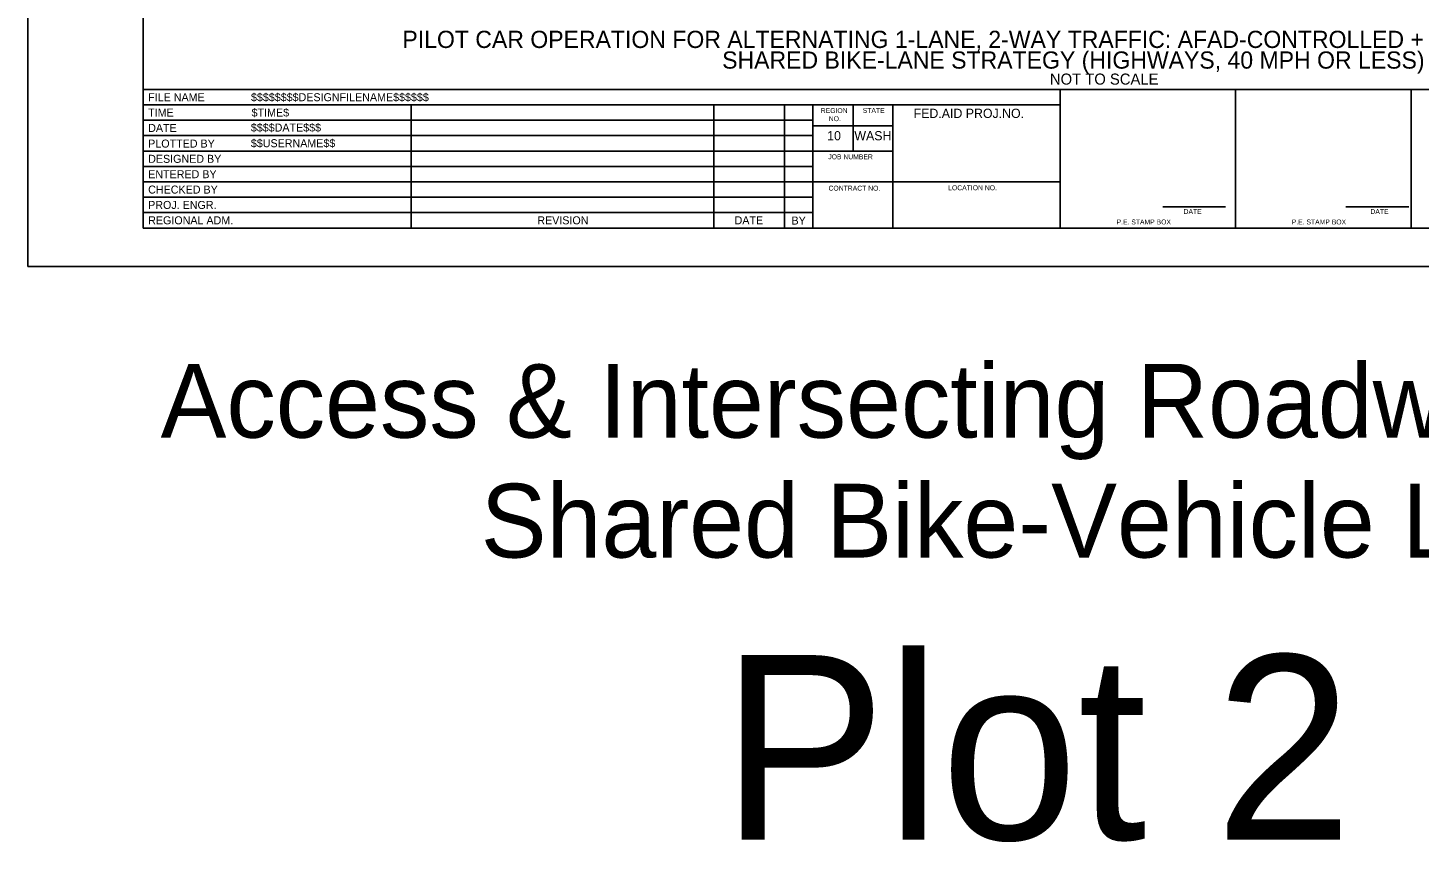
# Model space of a CAD drawing. Extents: x 99999.1 to 100095.7, y 99995 to 100010.7.
# Drawn here: x 100019.06 to 100030.38, y 99995.01 to 100001.63 of the extents above; entities that cross this region are included whole.
import ezdxf

# ---------------------------------------------------------------- set-up
doc = ezdxf.new("R2010")
doc.units = 0
for name, color, linetype in [('SH_DE_DetailHeading1Text', 7, 'Continuous'), ('SH_GI_PlotLimits', 7, 'Continuous'), ('SH_GI_SheetBorder', 7, 'Continuous'), ('SH_GI_SheetLocationText', 7, 'Continuous'), ('SH_GI_SheetTextInCells', 7, 'Continuous'), ('SH_GI_TitleBlockText', 7, 'Continuous')]:
    doc.layers.add(name, color=color, linetype=linetype)

msp = doc.modelspace()

# ---------------------------------------------------------------- linework, layer by layer
at = {"layer": 'SH_GI_PlotLimits'}
msp.add_lwpolyline([(100019.062, 99999.687), (100036.062, 99999.687), (100036.062, 100010.687), (100019.062, 100010.687)], close=True, dxfattribs=at)
at = {"layer": 'SH_GI_SheetBorder'}
for p, q in [((100020, 100010.375), (100020, 100000)), ((100020, 100001.126), (100035.75, 100001.126)), ((100027.457, 100000), (100027.457, 100001.126)), ((100028.883, 100000), (100028.883, 100001.126)), ((100030.309, 100001.126), (100030.309, 100000)), ((100020, 100001.001), (100027.457, 100001.001)), ((100022.179, 100001.001), (100022.179, 100000)), ((100024.641, 100001.001), (100024.641, 100000)), ((100025.216, 100001.001), (100025.216, 100000)), ((100025.445, 100001.001), (100025.445, 100000)), ((100025.772, 100000.625), (100025.772, 100001.001)), ((100026.096, 100000), (100026.096, 100001.001)), ((100020, 100000.876), (100022.182, 100000.876)), ((100022.182, 100000.876), (100025.447, 100000.876)), ((100026.096, 100000.831), (100025.447, 100000.831)), ((100020, 100000.751), (100022.182, 100000.751)), ((100022.182, 100000.751), (100025.447, 100000.751)), ((100020, 100000.625), (100025.447, 100000.625)), ((100026.096, 100000.625), (100025.447, 100000.625)), ((100020, 100000.5), (100025.447, 100000.5)), ((100020, 100000.375), (100025.447, 100000.375)), ((100027.457, 100000.375), (100025.447, 100000.375)), ((100020, 100000.25), (100025.447, 100000.25)), ((100020, 100000.125), (100025.447, 100000.125)), ((100028.29, 100000.173), (100028.802, 100000.173)), ((100029.78, 100000.173), (100030.291, 100000.173)), ((100020, 100000), (100035.75, 100000))]:
    msp.add_line(p, q, dxfattribs=at)

# ---------------------------------------------------------------- texts
at = {"layer": 'SH_DE_DetailHeading1Text'}
for s, height, p in [('PILOT CAR OPERATION FOR ALTERNATING 1-LANE, 2-WAY TRAFFIC: AFAD-CONTROLLED + TEMP. RUMBLE STRIPS', 0.14, (100022.108, 100001.464)), ('SHARED BIKE-LANE STRATEGY (HIGHWAYS, 40 MPH OR LESS)', 0.14, (100024.708, 100001.296)), ('NOT TO SCALE', 0.09, (100027.373, 100001.166))]:
    msp.add_text(s, height=height, rotation=360, dxfattribs=at).set_placement(p)
at = {"layer": 'SH_GI_SheetLocationText'}
for s, height, p in [('Access & Intersecting Roadway Details', 0.6, (100020.142, 99998.295)), ('Shared Bike-Vehicle Lane', 0.6, (100022.745, 99997.32)), ('Plot 2', 1.5, (100024.702, 99995.027))]:
    msp.add_text(s, height=height, dxfattribs=at).set_placement(p)
at = {"layer": 'SH_GI_SheetTextInCells'}
for s, height, p in [('FILE NAME', 0.0651, (100020.041, 100001.031)), ('TIME', 0.0651, (100020.041, 100000.906)), ('REGION', 0.04, (100025.51, 100000.935)), ('NO.', 0.04, (100025.575, 100000.869)), ('STATE', 0.04, (100025.851, 100000.936)), ('FED.AID PROJ.NO.', 0.07506, (100026.265, 100000.895)), ('DATE', 0.0651, (100020.041, 100000.781)), ('10', 0.0751, (100025.562, 100000.713)), ('WASH', 0.0751, (100025.783, 100000.713)), ('PLOTTED BY', 0.0651, (100020.041, 100000.654)), ('DESIGNED BY', 0.06505, (100020.041, 100000.53)), ('JOB NUMBER', 0.04, (100025.571, 100000.559)), ('ENTERED BY', 0.0651, (100020.041, 100000.405)), ('CHECKED BY', 0.0651, (100020.041, 100000.28)), ('CONTRACT NO.', 0.04003, (100025.573, 100000.304)), ('LOCATION NO.', 0.04003, (100026.546, 100000.307)), ('PROJ. ENGR.', 0.06505, (100020.041, 100000.155)), ('REGIONAL ADM.', 0.06505, (100020.041, 100000.03)), ('REVISION', 0.0651, (100023.205, 100000.03)), ('DATE', 0.04, (100028.46, 100000.114)), ('DATE', 0.04, (100029.979, 100000.114)), ('DATE', 0.0651, (100024.809, 100000.03)), ('BY', 0.0651, (100025.272, 100000.028)), ('P.E. STAMP BOX', 0.04003, (100027.915, 100000.029)), ('P.E. STAMP BOX', 0.04003, (100029.339, 100000.029))]:
    msp.add_text(s, height=height, dxfattribs=at).set_placement(p)
at = {"layer": 'SH_GI_TitleBlockText'}
for s, height, p in [('$$$$$$$$DESIGNFILENAME$$$$$$', 0.06505, (100020.877, 100001.031)), ('$TIME$', 0.0651, (100020.882, 100000.906)), ('$$$$DATE$$$', 0.06505, (100020.876, 100000.784)), ('$$USERNAME$$', 0.06505, (100020.876, 100000.657))]:
    msp.add_text(s, height=height, dxfattribs=at).set_placement(p)

doc.saveas('drawing.dxf')
